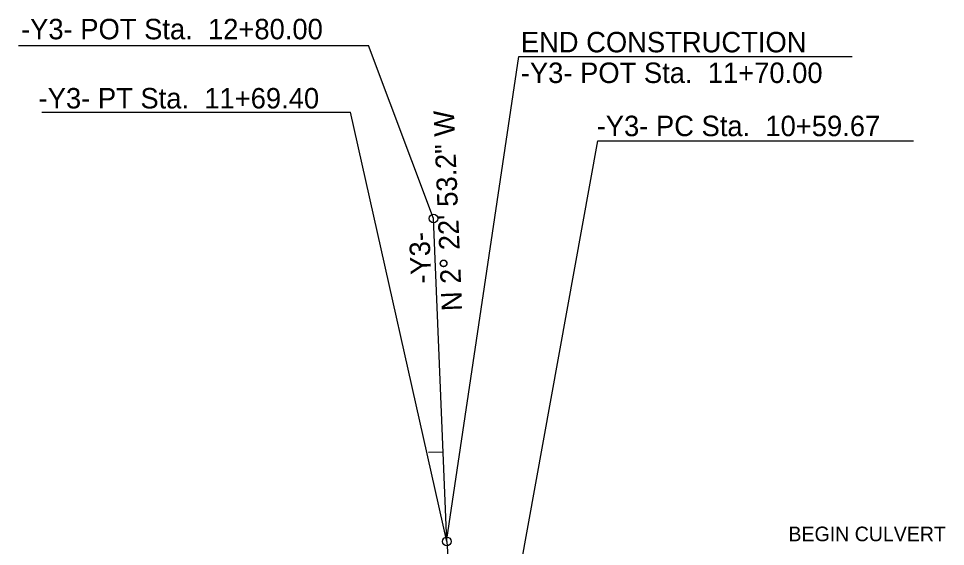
# Model space of a CAD drawing. Extents: x 1755545 to 1761252, y 736169 to 737766.
# Drawn here: x 1758783.2 to 1759100.4, y 737185.5 to 737366.2 of the extents above; entities that cross this region are included whole.
import ezdxf

# ---------------------------------------------------------------- set-up
doc = ezdxf.new("R2010")
doc.units = 0
for name, color, linetype in [('Prop Dimension', 7, 'Continuous'), ('Prop Horizontal Alignment', 7, 'Continuous'), ('Prop Horizontal Alignment Direction Label', 7, 'Continuous'), ('Prop Horizontal Alignment Station Label', 7, 'Continuous'), ('Prop Horizontal Alignment Tick Small', 7, 'Continuous')]:
    doc.layers.add(name, color=color, linetype=linetype)

msp = doc.modelspace()

# ---------------------------------------------------------------- linework, layer by layer
at = {"layer": 'Prop Horizontal Alignment'}
msp.add_line((1758929.75, 737187.22), (1758925.16, 737297.73), dxfattribs=at)
msp.add_arc((1761377.64, 737289.03), 2450, 182.38146, 184.94752, dxfattribs=at)
at = {"layer": 'Prop Horizontal Alignment Station Label'}
for p, q in [((1758783.16, 737356.96), (1758902.93, 737356.96)), ((1758925.16, 737297.73), (1758902.93, 737356.96)), ((1758929.73, 737187.82), (1758954.34, 737353.2)), ((1758954.34, 737353.2), (1759068.48, 737353.2)), ((1758791.13, 737334.16), (1758896.78, 737334.16)), ((1758929.75, 737187.22), (1758896.78, 737334.16)), ((1758936.77, 737077.73), (1758981.45, 737324.34)), ((1758981.45, 737324.34), (1759089.45, 737324.34))]:
    msp.add_line(p, q, dxfattribs=at)
for centre in [(1758925.16, 737297.73), (1758929.75, 737187.22)]:
    msp.add_circle(centre, 1.5, dxfattribs=at)
at = {"layer": 'Prop Horizontal Alignment Tick Small'}
msp.add_line((1758928.48, 737217.8), (1758923.49, 737217.59), dxfattribs=at)

# ---------------------------------------------------------------- texts
at = {"layer": 'Prop Dimension'}
msp.add_text('BEGIN CULVERT ', height=5, rotation=360, dxfattribs=at).set_placement((1759046.64, 737187.28))
at = {"layer": 'Prop Horizontal Alignment Direction Label'}
for s, p in [('N 2%%d 22\' 53.2" W', (1758934.99, 737266.18)), ('-Y3-', (1758924.5, 737275.56))]:
    msp.add_text(s, height=7, rotation=92.3815, dxfattribs=at).set_placement(p)
at = {"layer": 'Prop Horizontal Alignment Station Label'}
for s, p in [('-Y3- POT Sta.  12+80.00', (1758784.01, 737359.05)), ('-Y3- PT Sta.  11+69.40', (1758790.03, 737335.39)), ('-Y3- PC Sta.  10+59.67', (1758981, 737325.91))]:
    msp.add_text(s, height=7, rotation=360, dxfattribs=at).set_placement(p)
for s, p in [('END CONSTRUCTION', (1758955.04, 737354.59)), ('-Y3- POT Sta.  11+70.00', (1758955.04, 737344.09))]:
    msp.add_text(s, height=7, dxfattribs=at).set_placement(p)

doc.saveas('drawing.dxf')
